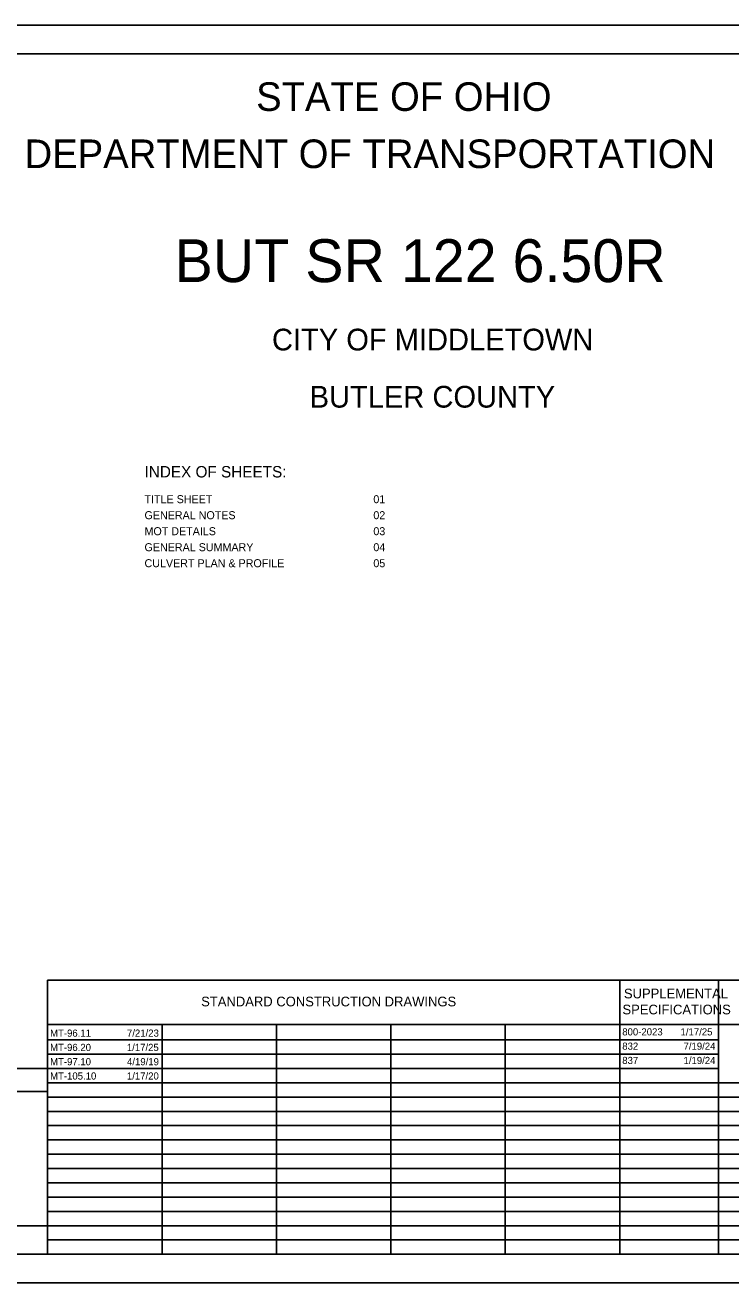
# Model space of a CAD drawing. Extents: x 0 to 34, y 0 to 22.
# Drawn here: x 9.76 to 22.09, y 0 to 22 of the extents above; entities that cross this region are included whole.
import ezdxf

# ---------------------------------------------------------------- set-up
doc = ezdxf.new("R2010")
doc.units = 0
for name, color, linetype in [('SH_Border', 7, 'Continuous'), ('SH_Cut_Line', 7, 'Continuous'), ('SH_Data', 7, 'Continuous'), ('SH_Text', 7, 'Continuous')]:
    doc.layers.add(name, color=color, linetype=linetype)

msp = doc.modelspace()

# ---------------------------------------------------------------- linework, layer by layer
at = {"layer": 'SH_Border'}
msp.add_lwpolyline([(1.5, 21.498), (33.5, 21.498), (33.5, 0.498), (1.5, 0.498)], close=True, dxfattribs=at)
at = {"layer": 'SH_Cut_Line'}
msp.add_lwpolyline([(0, -0.002), (34, -0.002), (34, 21.998), (0, 21.998)], close=True, dxfattribs=at)
at = {"layer": 'SH_Data'}
for p, q in [((10.15, 5.29), (23.6, 5.29)), ((10.15, 0.498), (10.15, 5.29)), ((20.15, 0.498), (20.15, 5.29)), ((21.875, 0.498), (21.875, 5.29)), ((10.15, 4.519), (23.6, 4.519)), ((12.15, 0.498), (12.15, 4.519)), ((14.15, 0.498), (14.15, 4.519)), ((16.15, 0.498), (16.15, 4.519)), ((18.15, 0.498), (18.15, 4.519)), ((10.15, 4.248), (21.875, 4.248)), ((10.15, 3.998), (21.875, 3.998)), ((10.15, 3.748), (7.35, 3.748)), ((10.15, 3.748), (21.875, 3.748)), ((10.15, 0.498), (10.15, 3.748)), ((10.15, 3.348), (7.35, 3.348)), ((10.15, 3.498), (23.6, 3.498)), ((10.15, 3.248), (23.6, 3.248)), ((10.15, 2.998), (23.6, 2.998)), ((10.15, 2.748), (23.6, 2.748)), ((10.15, 2.498), (23.6, 2.498)), ((10.15, 2.248), (23.6, 2.248)), ((10.15, 1.998), (23.6, 1.998)), ((10.15, 1.748), (23.6, 1.748)), ((10.15, 1.498), (23.6, 1.498)), ((10.15, 1.248), (23.6, 1.248)), ((10.15, 0.998), (23.6, 0.998)), ((10.15, 0.748), (23.6, 0.748)), ((10.15, 0.498), (7.35, 0.498))]:
    msp.add_line(p, q, dxfattribs=at)
msp.add_lwpolyline([(10.15, 0.498), (10.15, 0.998), (7.35, 0.998), (7.35, 0.498)], close=True, dxfattribs=at)

# ---------------------------------------------------------------- texts
at = {"layer": 'SH_Text'}
for s, height, p in [('STATE OF OHIO', 0.5, (13.795, 20.498)), ('DEPARTMENT OF TRANSPORTATION', 0.5, (9.747, 19.498)), ('BUT SR 122 6.50R', 0.75, (12.369, 17.503)), ('CITY OF MIDDLETOWN', 0.38, (14.072, 16.308)), ('BUTLER COUNTY', 0.38, (14.731, 15.308)), ('INDEX OF SHEETS:', 0.2, (11.844, 14.086)), ('TITLE SHEET', 0.14, (11.844, 13.636)), ('01', 0.14, (15.844, 13.636)), ('GENERAL NOTES', 0.14, (11.844, 13.356)), ('02', 0.14, (15.844, 13.356)), ('MOT DETAILS', 0.14, (11.844, 13.076)), ('03', 0.14, (15.844, 13.076)), ('GENERAL SUMMARY', 0.14, (11.844, 12.796)), ('04', 0.14, (15.844, 12.796)), ('CULVERT PLAN & PROFILE', 0.14, (11.844, 12.516)), ('05', 0.14, (15.844, 12.516)), ('SUPPLEMENTAL', 0.17, (20.224, 4.974)), ('STANDARD CONSTRUCTION DRAWINGS', 0.17, (12.834, 4.834)), ('SPECIFICATIONS', 0.17, (20.198, 4.694)), ('MT-96.11', 0.125, (10.193, 4.304)), ('7/21/23', 0.125, (11.537, 4.304)), ('800-2023', 0.125, (20.195, 4.326)), ('1/17/25', 0.125, (21.214, 4.326)), ('MT-96.20', 0.125, (10.193, 4.054)), ('1/17/25', 0.125, (11.535, 4.054)), ('832', 0.125, (20.195, 4.076)), ('7/19/24', 0.125, (21.266, 4.076)), ('MT-97.10', 0.125, (10.193, 3.804)), ('4/19/19', 0.125, (11.538, 3.804)), ('837', 0.125, (20.195, 3.826)), ('1/19/24', 0.125, (21.266, 3.826)), ('MT-105.10', 0.125, (10.193, 3.554)), ('1/17/20', 0.125, (11.536, 3.554))]:
    msp.add_text(s, height=height, dxfattribs=at).set_placement(p)

doc.saveas('drawing.dxf')
